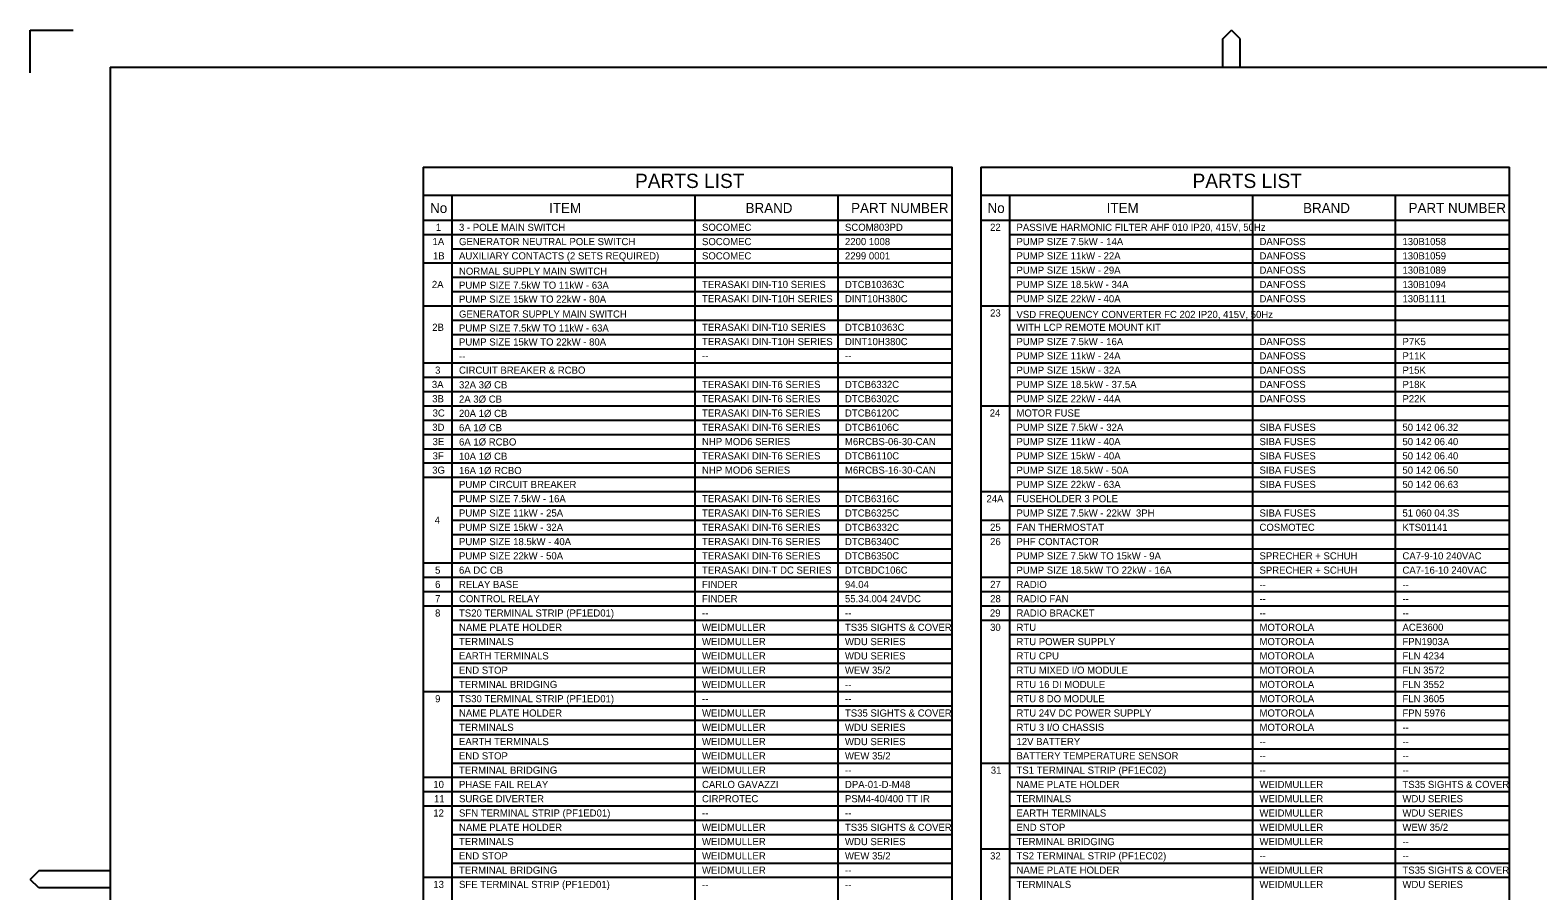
# Model space of a CAD drawing. Extents: x 0 to 841, y 0 to 594.
# Drawn here: x 0 to 527, y 293 to 594 of the extents above; entities that cross this region are included whole.
import ezdxf

# ---------------------------------------------------------------- set-up
doc = ezdxf.new("R2010")
doc.units = 0
for name, color, linetype in [('A1BORDER', 7, 'Continuous'), ('Default', 7, 'Continuous'), ('Level 1', 7, 'Continuous')]:
    doc.layers.add(name, color=color, linetype=linetype)

msp = doc.modelspace()

# ---------------------------------------------------------------- linework, layer by layer
at = {"layer": 'A1BORDER'}
for p, q in [((0, 594), (15, 594)), ((0, 579), (0, 594)), ((417.19, 591), (420.19, 594)), ((417.19, 581), (417.19, 591)), ((423.19, 591), (420.19, 594)), ((423.19, 581), (423.19, 591)), ((28, 581), (829, 581)), ((28, 581), (28, 15)), ((3, 299.76), (0, 296.76)), ((3, 293.76), (0, 296.76)), ((28, 299.76), (3, 299.76)), ((28, 293.76), (3, 293.76))]:
    msp.add_line(p, q, dxfattribs=at)
at = {"layer": 'Default'}
for p, q in [((137.5, 522.5), (322.5, 522.5)), ((147.5, 517.5), (322.5, 517.5)), ((137.5, 512.5), (322.5, 512.5)), ((342.5, 382.5), (517.5, 382.5)), ((342.5, 377.5), (517.5, 377.5)), ((342.5, 372.5), (517.5, 372.5)), ((342.5, 367.5), (517.5, 367.5)), ((342.5, 362.5), (517.5, 362.5)), ((342.5, 357.5), (517.5, 357.5)), ((342.5, 352.5), (517.5, 352.5)), ((342.5, 347.5), (517.5, 347.5)), ((342.5, 342.5), (517.5, 342.5)), ((332.5, 337.5), (517.5, 337.5)), ((342.5, 332.5), (517.5, 332.5)), ((342.5, 327.5), (517.5, 327.5)), ((342.5, 322.5), (517.5, 322.5)), ((342.5, 317.5), (517.5, 317.5)), ((342.5, 312.5), (517.5, 312.5)), ((332.5, 307.5), (517.5, 307.5)), ((342.5, 302.5), (517.5, 302.5)), ((342.5, 297.5), (517.5, 297.5))]:
    msp.add_line(p, q, dxfattribs=at)
at = {"layer": 'Level 1'}
for p, q in [((137.5, 546), (137.5, 107.5)), ((137.5, 546), (322.5, 546)), ((322.5, 107.5), (322.5, 546)), ((332.5, 546), (332.5, 112.5)), ((332.5, 546), (517.5, 546)), ((517.5, 112.5), (517.5, 546)), ((137.5, 536.25), (322.5, 536.25)), ((147.5, 536.25), (147.5, 107.5)), ((232.5, 536.25), (232.5, 107.5)), ((282.5, 536.25), (282.5, 107.5)), ((332.5, 536.25), (517.5, 536.25)), ((342.5, 536.25), (342.5, 112.5)), ((427.5, 536.25), (427.5, 112.5)), ((477.5, 536.25), (477.5, 112.5)), ((137.5, 527.5), (322.5, 527.5)), ((332.5, 527.5), (517.5, 527.5)), ((342.5, 522.5), (517.5, 522.5)), ((342.5, 517.5), (517.5, 517.5)), ((342.5, 512.5), (517.5, 512.5)), ((147.5, 507.5), (322.5, 507.5)), ((342.5, 507.5), (517.5, 507.5)), ((147.5, 502.5), (322.5, 502.5)), ((342.5, 502.5), (517.5, 502.5)), ((137.5, 497.5), (322.5, 497.5)), ((332.5, 497.5), (517.5, 497.5)), ((147.5, 492.5), (322.5, 492.5)), ((342.5, 492.5), (517.5, 492.5)), ((147.5, 487.5), (322.5, 487.5)), ((342.5, 487.5), (517.5, 487.5)), ((147.5, 482.5), (322.5, 482.5)), ((342.5, 482.5), (517.5, 482.5)), ((137.5, 477.5), (322.5, 477.5)), ((342.5, 477.5), (517.5, 477.5)), ((137.5, 472.5), (322.5, 472.5)), ((342.5, 472.5), (517.5, 472.5)), ((137.5, 467.5), (322.5, 467.5)), ((342.5, 467.5), (517.5, 467.5)), ((137.5, 462.5), (322.5, 462.5)), ((332.5, 462.5), (517.5, 462.5)), ((137.5, 457.5), (322.5, 457.5)), ((342.5, 457.5), (517.5, 457.5)), ((137.5, 452.5), (322.5, 452.5)), ((342.5, 452.5), (517.5, 452.5)), ((137.5, 447.5), (322.5, 447.5)), ((342.5, 447.5), (517.5, 447.5)), ((137.5, 442.5), (322.5, 442.5)), ((342.5, 442.5), (517.5, 442.5)), ((137.5, 437.5), (322.5, 437.5)), ((147.5, 432.5), (322.5, 432.5)), ((332.5, 432.5), (517.5, 432.5)), ((342.5, 437.5), (517.5, 437.5)), ((147.5, 427.5), (322.5, 427.5)), ((342.5, 427.5), (517.5, 427.5)), ((147.5, 422.5), (322.5, 422.5)), ((332.5, 422.5), (517.5, 422.5)), ((147.5, 417.5), (322.5, 417.5)), ((332.5, 417.5), (517.5, 417.5)), ((147.5, 412.5), (322.5, 412.5)), ((342.5, 412.5), (517.5, 412.5)), ((137.5, 407.5), (322.5, 407.5)), ((342.5, 407.5), (517.5, 407.5)), ((137.5, 402.5), (322.5, 402.5)), ((332.5, 402.5), (517.5, 402.5)), ((137.5, 397.5), (322.5, 397.5)), ((332.5, 397.5), (517.5, 397.5)), ((137.5, 392.5), (322.5, 392.5)), ((332.5, 392.5), (517.5, 392.5)), ((147.5, 387.5), (322.5, 387.5)), ((332.5, 387.5), (517.5, 387.5)), ((147.5, 382.5), (322.5, 382.5)), ((147.5, 377.5), (322.5, 377.5)), ((147.5, 372.5), (322.5, 372.5)), ((147.5, 367.5), (322.5, 367.5)), ((137.5, 362.5), (322.5, 362.5)), ((147.5, 357.5), (322.5, 357.5)), ((147.5, 352.5), (322.5, 352.5)), ((147.5, 347.5), (322.5, 347.5)), ((147.5, 342.5), (322.5, 342.5)), ((137.5, 332.5), (322.5, 332.5)), ((147.5, 337.5), (322.5, 337.5)), ((137.5, 327.5), (322.5, 327.5)), ((137.5, 322.5), (322.5, 322.5)), ((147.5, 317.5), (322.5, 317.5)), ((147.5, 312.5), (322.5, 312.5)), ((147.5, 307.5), (322.5, 307.5)), ((147.5, 302.5), (322.5, 302.5)), ((137.5, 297.5), (322.5, 297.5))]:
    msp.add_line(p, q, dxfattribs=at)

# ---------------------------------------------------------------- texts
at = {"layer": 'Default'}
for s, p in [('1', (141.88, 523.75)), ('3 - POLE MAIN SWITCH', (150, 523.75)), ('SOCOMEC', (235, 523.75)), ('SCOM803PD', (285, 523.75)), ('1A', (140.76, 518.75)), ('GENERATOR NEUTRAL POLE SWITCH', (150, 518.75)), ('SOCOMEC', (235, 518.75)), ('2200 1008', (285, 518.75)), ('1B', (140.88, 513.75)), ('AUXILIARY CONTACTS (2 SETS REQUIRED)', (150, 513.75)), ('SOCOMEC', (235, 513.75)), ('2299 0001', (285, 513.75)), ('RTU', (345, 383.75)), ('MOTOROLA', (430, 383.75)), ('ACE3600', (480, 383.75)), ('RTU POWER SUPPLY', (345, 378.75)), ('MOTOROLA', (430, 378.75)), ('FPN1903A', (480, 378.75)), ('RTU CPU', (345, 373.75)), ('MOTOROLA', (430, 373.75)), ('FLN 4234', (480, 373.75)), ('RTU MIXED I/O MODULE', (345, 368.75)), ('MOTOROLA', (430, 368.75)), ('FLN 3572', (480, 368.75)), ('RTU 16 DI MODULE', (345, 363.75)), ('MOTOROLA', (430, 363.75)), ('FLN 3552', (480, 363.75)), ('RTU 8 DO MODULE', (345, 358.75)), ('MOTOROLA', (430, 358.75)), ('FLN 3605', (480, 358.75)), ('RTU 24V DC POWER SUPPLY', (345, 353.75)), ('MOTOROLA', (430, 353.75)), ('FPN 5976', (480, 353.75)), ('RTU 3 I/O CHASSIS', (345, 348.75)), ('MOTOROLA', (430, 348.75)), ('--', (480, 348.75)), ('12V BATTERY', (345, 343.75)), ('--', (430, 343.75)), ('--', (480, 343.75)), ('BATTERY TEMPERATURE SENSOR', (345, 338.75)), ('--', (430, 338.75)), ('--', (480, 338.75)), ('31', (336.01, 333.75)), ('TS1 TERMINAL STRIP (PF1EC02)', (345, 333.75)), ('--', (430, 333.75)), ('--', (480, 333.75)), ('PHASE FAIL RELAY', (150, 328.75)), ('CARLO GAVAZZI', (235, 328.75)), ('DPA-01-D-M48', (285, 328.75)), ('NAME PLATE HOLDER', (345, 328.75)), ('WEIDMULLER', (430, 328.75)), ('TS35 SIGHTS & COVER', (480, 328.75)), ('SURGE DIVERTER', (150, 323.75)), ('CIRPROTEC', (235, 323.75)), ('PSM4-40/400 TT IR', (285, 323.75)), ('TERMINALS', (345, 323.75)), ('WEIDMULLER', (430, 323.75)), ('WDU SERIES', (480, 323.75)), ('EARTH TERMINALS', (345, 318.75)), ('WEIDMULLER', (430, 318.75)), ('WDU SERIES', (480, 318.75)), ('TERMINAL BRIDGING', (345, 308.75)), ('END STOP', (345, 313.75)), ('WEIDMULLER', (430, 313.75)), ('WEIDMULLER', (430, 308.75)), ('WEW 35/2', (480, 313.75)), ('32', (335.76, 303.75)), ('TS2 TERMINAL STRIP (PF1EC02)', (345, 303.75)), ('--', (480, 308.75)), ('NAME PLATE HOLDER', (345, 298.75)), ('WEIDMULLER', (430, 298.75)), ('--', (430, 303.75)), ('TS35 SIGHTS & COVER', (480, 298.75)), ('--', (480, 303.75)), ('TERMINALS', (345, 293.75)), ('WEIDMULLER', (430, 293.75)), ('WDU SERIES', (480, 293.75))]:
    msp.add_text(s, height=2.5, dxfattribs=at).set_placement(p)
at = {"layer": 'Level 1'}
for s, height, p in [('PARTS LIST', 5, (211.57, 538.75)), ('PARTS LIST', 5, (406.57, 538.75)), ('No', 3.5, (139.89, 530)), ('ITEM', 3.5, (181.54, 530)), ('BRAND', 3.5, (250.25, 530)), ('PART NUMBER', 3.5, (287.16, 530)), ('No', 3.5, (334.89, 530)), ('ITEM', 3.5, (376.54, 530)), ('BRAND', 3.5, (445.25, 530)), ('PART NUMBER', 3.5, (482.16, 530)), ('22', 2.5, (335.76, 523.75)), ('PASSIVE HARMONIC FILTER AHF 010 IP20, 415V, 50Hz', 2.5, (345, 523.75)), ('PUMP SIZE 7.5kW - 14A', 2.5, (345, 518.75)), ('DANFOSS', 2.5, (430, 518.75)), ('130B1058', 2.5, (480, 518.75)), ('PUMP SIZE 11kW - 22A', 2.5, (345, 513.75)), ('DANFOSS', 2.5, (430, 513.75)), ('130B1059', 2.5, (480, 513.75)), ('2A', 2.5, (140.51, 503.75)), ('NORMAL SUPPLY MAIN SWITCH', 2.5, (150, 508.38)), ('TERASAKI DIN-T10 SERIES', 2.5, (235, 503.75)), ('DTCB10363C', 2.5, (285, 503.75)), ('PUMP SIZE 15kW - 29A', 2.5, (345, 508.75)), ('PUMP SIZE 18.5kW - 34A', 2.5, (345, 503.75)), ('DANFOSS', 2.5, (430, 508.75)), ('DANFOSS', 2.5, (430, 503.75)), ('130B1089', 2.5, (480, 508.75)), ('130B1094', 2.5, (480, 503.75)), ('PUMP SIZE 7.5kW TO 11kW - 63A', 2.5, (150, 503.5)), ('PUMP SIZE 15kW TO 22kW - 80A', 2.5, (150, 498.62)), ('TERASAKI DIN-T10H SERIES', 2.5, (235, 498.75)), ('DINT10H380C', 2.5, (285, 498.75)), ('PUMP SIZE 22kW - 40A', 2.5, (345, 498.75)), ('DANFOSS', 2.5, (430, 498.75)), ('130B1111', 2.5, (480, 498.75)), ('GENERATOR SUPPLY MAIN SWITCH', 2.5, (150, 493.38)), ('23', 2.5, (335.76, 493.75)), ('VSD FREQUENCY CONVERTER FC 202 IP20, 415V, 50Hz', 2.5, (345, 493.25)), ('2B', 2.5, (140.63, 488.75)), ('PUMP SIZE 7.5kW TO 11kW - 63A', 2.5, (150, 488.5)), ('TERASAKI DIN-T10 SERIES', 2.5, (235, 488.75)), ('DTCB10363C', 2.5, (285, 488.75)), ('WITH LCP REMOTE MOUNT KIT', 2.5, (345, 488.75)), ('PUMP SIZE 15kW TO 22kW - 80A', 2.5, (150, 483.62)), ('TERASAKI DIN-T10H SERIES', 2.5, (235, 483.75)), ('DINT10H380C', 2.5, (285, 483.75)), ('PUMP SIZE 7.5kW - 16A ', 2.5, (345, 483.75)), ('DANFOSS', 2.5, (430, 483.75)), ('P7K5', 2.5, (480, 483.75)), ('PUMP SIZE 11kW - 24A', 2.5, (345, 478.75)), ('DANFOSS', 2.5, (430, 478.75)), ('P11K', 2.5, (480, 478.75)), ('3', 2.5, (141.63, 473.75)), ('--', 2.5, (150, 478.62)), ('CIRCUIT BREAKER & RCBO', 2.5, (150, 473.75)), ('--', 2.5, (235, 478.75)), ('--', 2.5, (285, 478.75)), ('PUMP SIZE 15kW - 32A', 2.5, (345, 473.75)), ('DANFOSS', 2.5, (430, 473.75)), ('P15K', 2.5, (480, 473.75)), ('3A', 2.5, (140.51, 468.75)), ('32A 3%%c CB', 2.5, (150, 468.62)), ('TERASAKI DIN-T6 SERIES', 2.5, (235, 468.75)), ('DTCB6332C', 2.5, (285, 468.75)), ('PUMP SIZE 18.5kW - 37.5A', 2.5, (345, 468.75)), ('DANFOSS', 2.5, (430, 468.75)), ('P18K', 2.5, (480, 468.75)), ('3B', 2.5, (140.63, 463.75)), ('2A 3%%c CB', 2.5, (150, 463.62)), ('TERASAKI DIN-T6 SERIES', 2.5, (235, 463.75)), ('DTCB6302C', 2.5, (285, 463.75)), ('PUMP SIZE 22kW - 44A', 2.5, (345, 463.75)), ('DANFOSS', 2.5, (430, 463.75)), ('P22K', 2.5, (480, 463.75)), ('3C', 2.5, (140.76, 458.75)), ('20A 1%%c CB', 2.5, (150, 458.62)), ('TERASAKI DIN-T6 SERIES', 2.5, (235, 458.75)), ('DTCB6120C', 2.5, (285, 458.75)), ('24', 2.5, (335.63, 458.75)), ('MOTOR FUSE', 2.5, (345, 458.75)), ('3D', 2.5, (140.63, 453.75)), ('6A 1%%c CB', 2.5, (150, 453.62)), ('TERASAKI DIN-T6 SERIES', 2.5, (235, 453.75)), ('DTCB6106C', 2.5, (285, 453.75)), ('PUMP SIZE 7.5kW - 32A ', 2.5, (345, 453.75)), ('SIBA FUSES', 2.5, (430, 453.75)), ('50 142 06.32', 2.5, (480, 453.75)), ('3E', 2.5, (140.76, 448.75)), ('6A 1%%c RCBO', 2.5, (150, 448.62)), ('NHP MOD6 SERIES', 2.5, (235, 448.75)), ('M6RCBS-06-30-CAN', 2.5, (285, 448.75)), ('PUMP SIZE 11kW - 40A', 2.5, (345, 448.75)), ('SIBA FUSES', 2.5, (430, 448.75)), ('50 142 06.40', 2.5, (480, 448.75)), ('3F', 2.5, (140.76, 443.75)), ('10A 1%%c CB', 2.5, (150, 443.62)), ('TERASAKI DIN-T6 SERIES', 2.5, (235, 443.75)), ('DTCB6110C', 2.5, (285, 443.75)), ('PUMP SIZE 15kW - 40A', 2.5, (345, 443.75)), ('SIBA FUSES', 2.5, (430, 443.75)), ('50 142 06.40', 2.5, (480, 443.75)), ('3G', 2.5, (140.63, 438.75)), ('16A 1%%c RCBO', 2.5, (150, 438.63)), ('NHP MOD6 SERIES', 2.5, (235, 438.75)), ('M6RCBS-16-30-CAN', 2.5, (285, 438.75)), ('PUMP SIZE 18.5kW - 50A', 2.5, (345, 438.75)), ('SIBA FUSES', 2.5, (430, 438.75)), ('50 142 06.50', 2.5, (480, 438.75)), ('PUMP CIRCUIT BREAKER', 2.5, (150, 433.75)), ('PUMP SIZE 22kW - 63A', 2.5, (345, 433.75)), ('SIBA FUSES', 2.5, (430, 433.75)), ('50 142 06.63', 2.5, (480, 433.75)), ('PUMP SIZE 7.5kW - 16A', 2.5, (150, 428.75)), ('TERASAKI DIN-T6 SERIES', 2.5, (235, 428.75)), ('DTCB6316C', 2.5, (285, 428.75)), ('24A', 2.5, (334.51, 428.75)), ('FUSEHOLDER 3 POLE', 2.5, (345, 428.75)), ('4', 2.5, (141.5, 421.25)), ('PUMP SIZE 11kW - 25A', 2.5, (150, 423.75)), ('TERASAKI DIN-T6 SERIES', 2.5, (235, 423.75)), ('DTCB6325C', 2.5, (285, 423.75)), ('PUMP SIZE 7.5kW - 22kW  3PH', 2.5, (345, 423.75)), ('SIBA FUSES', 2.5, (430, 423.75)), ('51 060 04.3S', 2.5, (480, 423.75)), ('PUMP SIZE 15kW - 32A', 2.5, (150, 418.75)), ('TERASAKI DIN-T6 SERIES', 2.5, (235, 418.75)), ('DTCB6332C', 2.5, (285, 418.75)), ('25', 2.5, (335.76, 418.75)), ('FAN THERMOSTAT', 2.5, (345, 418.75)), ('COSMOTEC', 2.5, (430, 418.75)), ('KTS01141', 2.5, (480, 418.75)), ('PUMP SIZE 18.5kW - 40A', 2.5, (150, 413.75)), ('PUMP SIZE 22kW - 50A', 2.5, (150, 408.75)), ('TERASAKI DIN-T6 SERIES', 2.5, (235, 413.75)), ('DTCB6340C', 2.5, (285, 413.75)), ('26', 2.5, (335.76, 413.75)), ('PHF CONTACTOR', 2.5, (345, 413.75)), ('PUMP SIZE 7.5kW TO 15kW - 9A', 2.5, (345, 408.75)), ('5', 2.5, (141.63, 403.75)), ('6A DC CB', 2.5, (150, 403.75)), ('TERASAKI DIN-T6 SERIES', 2.5, (235, 408.75)), ('TERASAKI DIN-T DC SERIES', 2.5, (235, 403.75)), ('DTCB6350C', 2.5, (285, 408.75)), ('DTCBDC106C', 2.5, (285, 403.75)), ('PUMP SIZE 18.5kW TO 22kW - 16A', 2.5, (345, 403.75)), ('SPRECHER + SCHUH', 2.5, (430, 408.75)), ('SPRECHER + SCHUH', 2.5, (430, 403.75)), ('CA7-9-10 240VAC', 2.5, (480, 408.75)), ('CA7-16-10 240VAC', 2.5, (480, 403.75)), ('6', 2.5, (141.63, 398.75)), ('RELAY BASE', 2.5, (150, 398.75)), ('FINDER', 2.5, (235, 398.75)), ('94.04', 2.5, (285, 398.75)), ('27', 2.5, (335.79, 398.75)), ('RADIO', 2.5, (345, 398.75)), ('7', 2.5, (141.63, 393.75)), ('CONTROL RELAY', 2.5, (150, 393.75)), ('FINDER', 2.5, (235, 393.75)), ('55.34.004 24VDC', 2.5, (285, 393.75)), ('28', 2.5, (335.79, 393.75)), ('RADIO FAN', 2.5, (345, 393.75)), ('--', 2.5, (430, 398.75)), ('--', 2.5, (480, 398.75)), ('8', 2.5, (141.63, 388.75)), ('TS20 TERMINAL STRIP (PF1ED01)', 2.5, (150, 388.75)), ('29', 2.5, (335.71, 388.75)), ('RADIO BRACKET', 2.5, (345, 388.75)), ('--', 2.5, (430, 393.75)), ('--', 2.5, (480, 393.75)), ('NAME PLATE HOLDER', 2.5, (150, 383.75)), ('WEIDMULLER', 2.5, (235, 383.75)), ('--', 2.5, (235, 388.75)), ('TS35 SIGHTS & COVER', 2.5, (285, 383.75)), ('--', 2.5, (285, 388.75)), ('30', 2.5, (335.76, 383.75)), ('--', 2.5, (430, 388.75)), ('--', 2.5, (480, 388.75)), ('TERMINALS', 2.5, (150, 378.75)), ('WEIDMULLER', 2.5, (235, 378.75)), ('WDU SERIES', 2.5, (285, 378.75)), ('EARTH TERMINALS', 2.5, (150, 373.75)), ('WEIDMULLER', 2.5, (235, 373.75)), ('WDU SERIES', 2.5, (285, 373.75)), ('END STOP', 2.5, (150, 368.75)), ('WEIDMULLER', 2.5, (235, 368.75)), ('WEW 35/2', 2.5, (285, 368.75)), ('TERMINAL BRIDGING', 2.5, (150, 363.75)), ('WEIDMULLER', 2.5, (235, 363.75)), ('--', 2.5, (285, 363.75)), ('9', 2.5, (141.64, 358.75)), ('TS30 TERMINAL STRIP (PF1ED01)', 2.5, (150, 358.75)), ('--', 2.5, (235, 358.75)), ('--', 2.5, (285, 358.75)), ('NAME PLATE HOLDER', 2.5, (150, 353.75)), ('WEIDMULLER', 2.5, (235, 353.75)), ('TS35 SIGHTS & COVER', 2.5, (285, 353.75)), ('TERMINALS', 2.5, (150, 348.75)), ('WEIDMULLER', 2.5, (235, 348.75)), ('WDU SERIES', 2.5, (285, 348.75)), ('EARTH TERMINALS', 2.5, (150, 343.75)), ('WEIDMULLER', 2.5, (235, 343.75)), ('WDU SERIES', 2.5, (285, 343.75)), ('END STOP', 2.5, (150, 338.75)), ('WEIDMULLER', 2.5, (235, 338.75)), ('WEW 35/2', 2.5, (285, 338.75)), ('TERMINAL BRIDGING', 2.5, (150, 333.75)), ('WEIDMULLER', 2.5, (235, 333.75)), ('--', 2.5, (285, 333.75)), ('10', 2.5, (141.01, 328.75)), ('11', 2.5, (141.25, 323.75)), ('12', 2.5, (141.01, 318.75)), ('SFN TERMINAL STRIP (PF1ED01)', 2.5, (150, 318.75)), ('--', 2.5, (235, 318.75)), ('--', 2.5, (285, 318.75)), ('TERMINALS', 2.5, (150, 308.75)), ('NAME PLATE HOLDER', 2.5, (150, 313.75)), ('WEIDMULLER', 2.5, (235, 313.75)), ('WEIDMULLER', 2.5, (235, 308.75)), ('WDU SERIES', 2.5, (285, 308.75)), ('TS35 SIGHTS & COVER', 2.5, (285, 313.75)), ('END STOP', 2.5, (150, 303.75)), ('WEIDMULLER', 2.5, (235, 303.75)), ('WEW 35/2', 2.5, (285, 303.75)), ('TERMINAL BRIDGING', 2.5, (150, 298.75)), ('WEIDMULLER', 2.5, (235, 298.75)), ('13', 2.5, (141.01, 293.75)), ('SFE TERMINAL STRIP (PF1ED01)', 2.5, (150, 293.75)), ('--', 2.5, (285, 298.75)), ('--', 2.5, (235, 293.75)), ('--', 2.5, (285, 293.75))]:
    msp.add_text(s, height=height, dxfattribs=at).set_placement(p)

doc.saveas('drawing.dxf')
